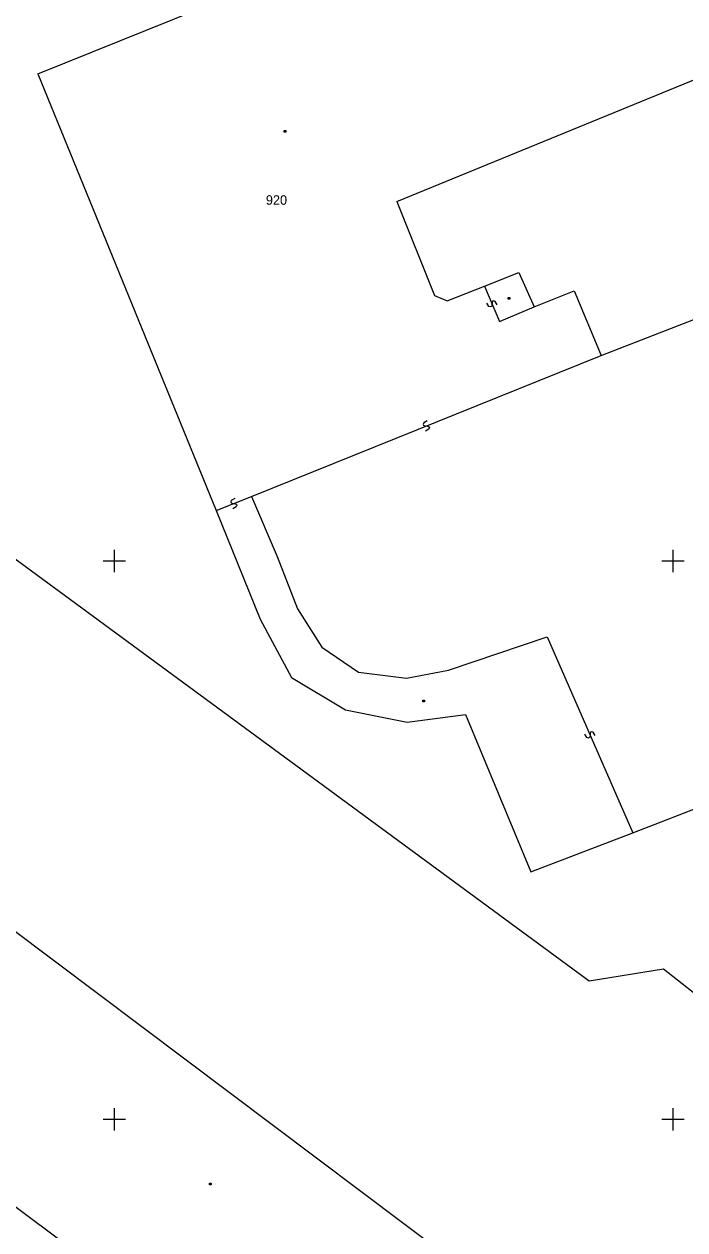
# Model space of a CAD drawing. Extents: x -492379 to -491966, y -1126153 to -1125860.
# Drawn here: x -492094.8 to -492059.4, y -1126025.9 to -1125961.2 of the extents above; entities that cross this region are included whole.
import ezdxf

# ---------------------------------------------------------------- set-up
doc = ezdxf.new("R2010")
doc.units = 0
doc.layers.add('katastrální mapa', color=7, linetype='Continuous')
doc.layers.add('síť', color=7, linetype='Continuous')

msp = doc.modelspace()

# ---------------------------------------------------------------- linework, layer by layer
at = {"layer": 'katastrální mapa'}
for p, q in [((-492074.82, -1125970.7), (-492046.06, -1125958.91)), ((-492094.1, -1125963.84), (-492083.13, -1125959.41)), ((-492094.1, -1125963.84), (-492084.53, -1125987.3)), ((-492080.87, -1125966.88), (-492080.78, -1125966.88)), ((-492080.87, -1125966.97), (-492080.87, -1125966.88)), ((-492080.78, -1125966.97), (-492080.87, -1125966.97)), ((-492080.78, -1125966.88), (-492080.78, -1125966.97)), ((-492123.53, -1125969.16), (-492064.49, -1126012.56)), ((-492074.82, -1125970.7), (-492072.81, -1125975.75)), ((-492063.85, -1125978.97), (-492045.92, -1125971.96)), ((-492070.12, -1125975.25), (-492068.28, -1125974.51)), ((-492068.28, -1125974.51), (-492067.45, -1125976.36)), ((-492072.13, -1125976.04), (-492070.12, -1125975.25)), ((-492070.12, -1125975.25), (-492069.31, -1125977.14)), ((-492072.81, -1125975.75), (-492072.13, -1125976.04)), ((-492069.68, -1125976.05), (-492069.71, -1125976.13)), ((-492069.62, -1125976.03), (-492069.68, -1125976.05)), ((-492069.55, -1125976.06), (-492069.62, -1125976.03)), ((-492069.44, -1125976.24), (-492069.55, -1125976.06)), ((-492068.84, -1125975.85), (-492068.75, -1125975.85)), ((-492068.84, -1125975.94), (-492068.84, -1125975.85)), ((-492068.75, -1125975.94), (-492068.84, -1125975.94)), ((-492068.75, -1125975.85), (-492068.75, -1125975.94)), ((-492067.45, -1125976.36), (-492065.3, -1125975.5)), ((-492065.3, -1125975.5), (-492063.85, -1125978.97)), ((-492069.88, -1125976.33), (-492069.99, -1125976.15)), ((-492069.81, -1125976.36), (-492069.88, -1125976.33)), ((-492069.75, -1125976.34), (-492069.81, -1125976.36)), ((-492069.72, -1125976.26), (-492069.75, -1125976.34)), ((-492069.71, -1125976.13), (-492069.72, -1125976.26)), ((-492069.31, -1125977.14), (-492067.45, -1125976.36)), ((-492082.64, -1125986.55), (-492063.85, -1125978.97)), ((-492073.38, -1125982.59), (-492073.41, -1125982.67)), ((-492073.2, -1125982.48), (-492073.38, -1125982.59)), ((-492073.41, -1125982.67), (-492073.39, -1125982.72)), ((-492073.39, -1125982.72), (-492073.31, -1125982.75)), ((-492073.31, -1125982.75), (-492073.18, -1125982.77)), ((-492073.11, -1125982.93), (-492073.29, -1125983.04)), ((-492073.18, -1125982.77), (-492073.1, -1125982.8)), ((-492073.08, -1125982.85), (-492073.11, -1125982.93)), ((-492073.1, -1125982.8), (-492073.08, -1125982.85)), ((-492084.53, -1125987.3), (-492082.64, -1125986.55)), ((-492083.72, -1125986.75), (-492083.75, -1125986.83)), ((-492083.75, -1125986.83), (-492083.73, -1125986.89)), ((-492083.73, -1125986.89), (-492083.65, -1125986.92)), ((-492083.53, -1125986.65), (-492083.72, -1125986.75)), ((-492083.65, -1125986.92), (-492083.52, -1125986.93)), ((-492083.45, -1125987.1), (-492083.64, -1125987.2)), ((-492083.52, -1125986.93), (-492083.44, -1125986.96)), ((-492083.42, -1125987.02), (-492083.45, -1125987.1)), ((-492083.44, -1125986.96), (-492083.42, -1125987.02)), ((-492082.64, -1125986.55), (-492081.25, -1125989.77)), ((-492084.53, -1125987.3), (-492082.16, -1125993.14)), ((-492081.25, -1125989.77), (-492080.17, -1125992.58)), ((-492080.17, -1125992.58), (-492078.85, -1125994.63)), ((-492082.16, -1125993.14), (-492080.49, -1125996.27)), ((-492072.05, -1125995.88), (-492066.75, -1125994.09)), ((-492066.75, -1125994.09), (-492062.15, -1126004.61)), ((-492078.85, -1125994.63), (-492076.88, -1125995.99)), ((-492062.15, -1126004.61), (-492037.06, -1125994.84)), ((-492076.88, -1125995.99), (-492074.31, -1125996.31)), ((-492074.31, -1125996.31), (-492072.05, -1125995.88)), ((-492080.49, -1125996.27), (-492077.59, -1125998)), ((-492073.43, -1125997.48), (-492073.34, -1125997.48)), ((-492073.43, -1125997.57), (-492073.43, -1125997.48)), ((-492073.34, -1125997.48), (-492073.34, -1125997.57)), ((-492077.59, -1125998), (-492074.28, -1125998.67)), ((-492073.34, -1125997.57), (-492073.43, -1125997.57)), ((-492074.28, -1125998.67), (-492071.13, -1125998.25)), ((-492071.13, -1125998.25), (-492067.62, -1126006.7)), ((-492064.62, -1125999.49), (-492064.73, -1125999.31)), ((-492064.45, -1125999.42), (-492064.48, -1125999.5)), ((-492064.42, -1125999.2), (-492064.45, -1125999.28)), ((-492064.45, -1125999.28), (-492064.45, -1125999.42)), ((-492064.36, -1125999.18), (-492064.42, -1125999.2)), ((-492064.28, -1125999.21), (-492064.36, -1125999.18)), ((-492064.17, -1125999.39), (-492064.28, -1125999.21)), ((-492064.54, -1125999.52), (-492064.62, -1125999.49)), ((-492064.48, -1125999.5), (-492064.54, -1125999.52)), ((-492067.62, -1126006.7), (-492062.15, -1126004.61)), ((-492095.59, -1126009.69), (-492068.35, -1126030.18)), ((-492064.49, -1126012.56), (-492060.51, -1126011.92)), ((-492060.51, -1126011.92), (-492055.51, -1126015.84)), ((-492102.61, -1126019.24), (-492075.28, -1126039.67)), ((-492084.88, -1126023.43), (-492084.79, -1126023.43)), ((-492084.88, -1126023.52), (-492084.88, -1126023.43)), ((-492084.79, -1126023.52), (-492084.88, -1126023.52)), ((-492084.79, -1126023.43), (-492084.79, -1126023.52))]:
    msp.add_line(p, q, dxfattribs=at)
at = {"layer": 'síť'}
for p, q in [((-492090, -1125989.4), (-492090, -1125990.6)), ((-492060, -1125989.4), (-492060, -1125990.6)), ((-492090.6, -1125990), (-492089.4, -1125990)), ((-492060.6, -1125990), (-492059.4, -1125990)), ((-492090, -1126019.4), (-492090, -1126020.6)), ((-492060, -1126019.4), (-492060, -1126020.6)), ((-492090.6, -1126020), (-492089.4, -1126020)), ((-492060.6, -1126020), (-492059.4, -1126020))]:
    msp.add_line(p, q, dxfattribs=at)

# ---------------------------------------------------------------- texts
at = {"layer": 'katastrální mapa'}
msp.add_text('920', height=0.51, dxfattribs=at).set_placement((-492081.86, -1125970.87))

doc.saveas('drawing.dxf')
